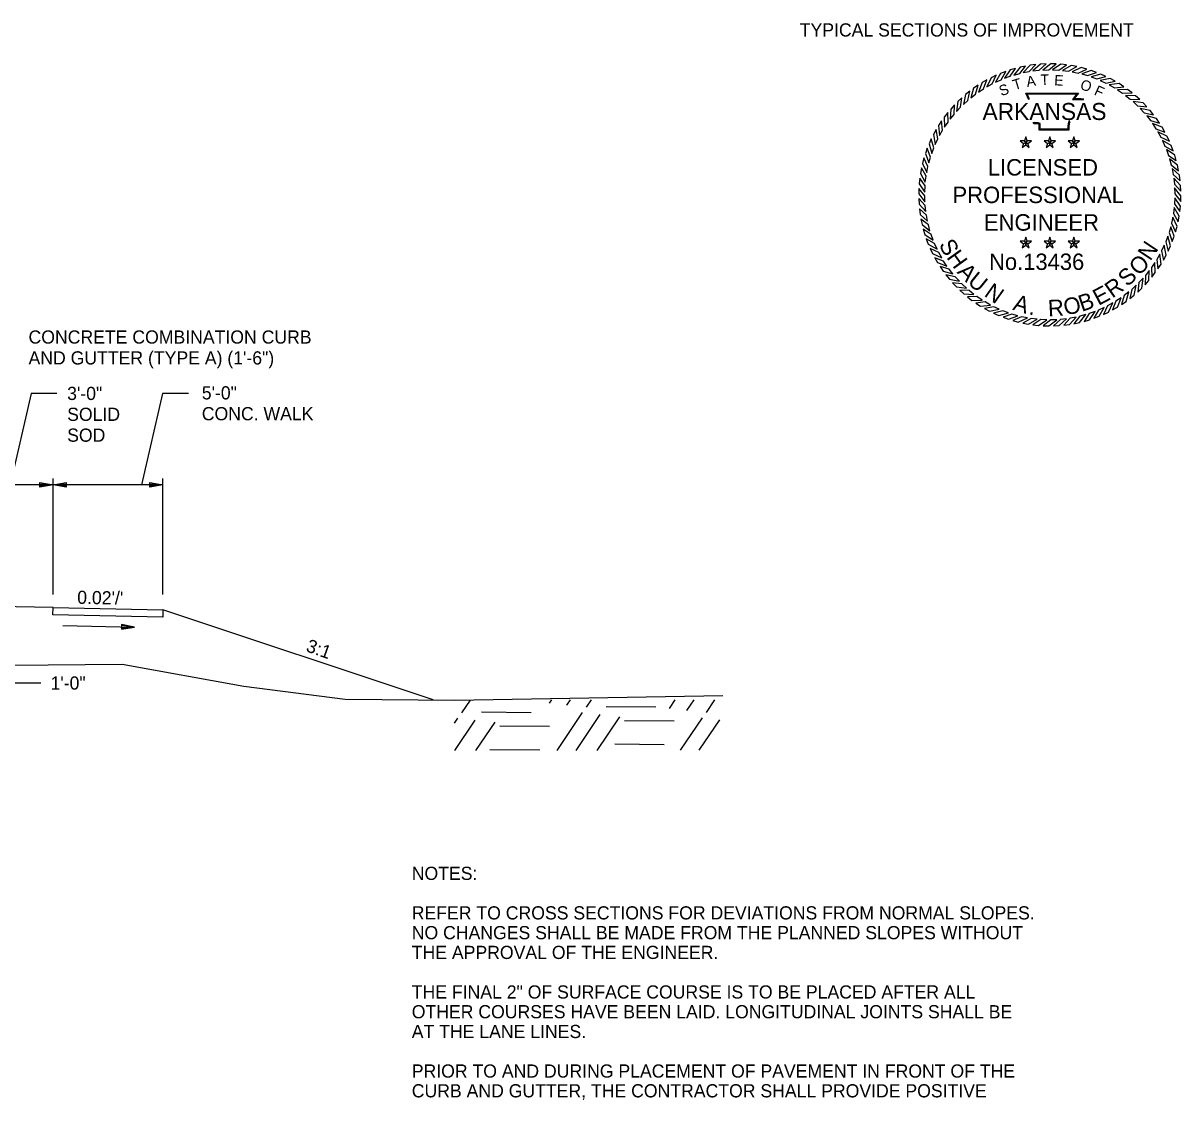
# Model space of a CAD drawing. Extents: x 1001270 to 1003428, y 1840152 to 1842912.
# Drawn here: x 1001375.8 to 1001428.5, y 1842848.3 to 1842897.3 of the extents above; entities that cross this region are included whole.
import ezdxf

# ---------------------------------------------------------------- set-up
doc = ezdxf.new("R2010")
doc.units = 0
for name, color, linetype in [('1', 7, 'Continuous'), ('19', 7, 'Continuous'), ('20', 7, 'Continuous'), ('8', 7, 'Continuous'), ('G-ANNO-SYMB', 7, 'Continuous')]:
    doc.layers.add(name, color=color, linetype=linetype)

# ---------------------------------------------------------------- blocks, each defined once
blk = doc.blocks.new('TM')
at = {"layer": '8'}
for p, q in [((-120.309, 21.181), (-119.787, -20.829)), ((0, 0), (-120.309, 21.181)), ((-31.382, 2.945), (-120.176, 10.512)), ((-119.787, -20.829), (0, 0)), ((-119.911, -10.826), (-31.307, -3.057))]:
    blk.add_line(p, q, dxfattribs=at)

msp = doc.modelspace()

# ---------------------------------------------------------------- linework, layer by layer
at = {"layer": '19'}
for p, q in [((1001376.15, 1842880.471), (1001375.194, 1842876.314)), ((1001377.329, 1842880.471), (1001376.15, 1842880.471)), ((1001382.133, 1842880.471), (1001381.176, 1842876.314)), ((1001383.312, 1842880.471), (1001382.133, 1842880.471)), ((1001382.155, 1842876.314), (1001372.655, 1842876.314)), ((1001376.555, 1842876.209), (1001376.555, 1842876.419)), ((1001376.555, 1842876.419), (1001377.155, 1842876.314)), ((1001376.555, 1842876.364), (1001376.995, 1842876.329)), ((1001377.155, 1842876.314), (1001376.555, 1842876.209)), ((1001376.995, 1842876.299), (1001376.555, 1842876.259)), ((1001377.155, 1842871.324), (1001377.155, 1842876.614)), ((1001377.155, 1842876.314), (1001377.755, 1842876.419)), ((1001377.755, 1842876.209), (1001377.155, 1842876.314)), ((1001377.315, 1842876.329), (1001377.755, 1842876.364)), ((1001377.755, 1842876.259), (1001377.315, 1842876.299)), ((1001377.755, 1842876.419), (1001377.755, 1842876.209)), ((1001381.555, 1842876.209), (1001381.555, 1842876.419)), ((1001381.555, 1842876.419), (1001382.155, 1842876.314)), ((1001381.555, 1842876.364), (1001381.995, 1842876.329)), ((1001382.155, 1842876.314), (1001381.555, 1842876.209)), ((1001381.995, 1842876.299), (1001381.555, 1842876.259)), ((1001382.155, 1842871.324), (1001382.155, 1842876.614)), ((1001377.156, 1842870.731), (1001374.155, 1842870.79)), ((1001377.143, 1842870.398), (1001377.156, 1842870.731)), ((1001377.156, 1842870.731), (1001382.155, 1842870.63)), ((1001377.156, 1842870.731), (1001377.156, 1842870.731)), ((1001382.155, 1842870.63), (1001382.142, 1842870.298)), ((1001394.456, 1842866.53), (1001382.155, 1842870.63)), ((1001382.142, 1842870.298), (1001377.143, 1842870.398)), ((1001375.155, 1842867.304), (1001376.604, 1842867.304)), ((1001375.155, 1842867.304), (1001376.604, 1842867.304)), ((1001395.763, 1842865.94), (1001396.155, 1842866.523)), ((1001399.749, 1842866.374), (1001399.855, 1842866.524)), ((1001400.544, 1842866.283), (1001400.709, 1842866.527)), ((1001401.439, 1842866.19), (1001401.665, 1842866.529)), ((1001405.203, 1842866.135), (1001405.465, 1842866.53)), ((1001405.998, 1842866.043), (1001406.329, 1842866.532)), ((1001406.893, 1842865.951), (1001407.274, 1842866.525)), ((1001396.652, 1842865.979), (1001398.912, 1842865.958)), ((1001400.101, 1842864.227), (1001401.253, 1842865.948)), ((1001400.956, 1842864.23), (1001402.048, 1842865.856)), ((1001401.911, 1842864.232), (1001402.943, 1842865.764)), ((1001402.326, 1842866.22), (1001404.587, 1842866.208)), ((1001395.424, 1842865.472), (1001395.578, 1842865.698)), ((1001395.446, 1842864.224), (1001396.372, 1842865.606)), ((1001396.401, 1842864.226), (1001397.268, 1842865.514)), ((1001397.492, 1842865.35), (1001399.752, 1842865.329)), ((1001403.157, 1842865.591), (1001405.427, 1842865.579)), ((1001405.711, 1842864.233), (1001406.707, 1842865.709)), ((1001406.566, 1842864.235), (1001407.502, 1842865.617)), ((1001397.039, 1842864.271), (1001399.31, 1842864.258)), ((1001402.715, 1842864.521), (1001404.974, 1842864.5))]:
    msp.add_line(p, q, dxfattribs=at)
for points in [[(1001312.476, 1842875.841), (1001316.166, 1842875.618), (1001320.348, 1842874.967), (1001324.071, 1842873.734), (1001333.313, 1842870.336), (1001335.792, 1842869.514), (1001340.406, 1842868.154), (1001345.958, 1842868.399), (1001354.686, 1842868.327), (1001358.509, 1842868.349), (1001367.384, 1842868.023), (1001373.548, 1842868.092), (1001380.3, 1842868.156), (1001385.837, 1842867.152), (1001390.452, 1842866.558), (1001395.437, 1842866.523)], [(1001395.437, 1842866.523), (1001407.642, 1842866.726)]]:
    msp.add_lwpolyline(points, dxfattribs=at)
at = {"layer": '20'}
msp.add_line((1001377.594, 1842869.911), (1001380.864, 1842869.846), dxfattribs=at)
at = {"layer": 'G-ANNO-SYMB'}
for points in [[(1001420.96, 1842895.277), (1001420.714, 1842895.205), (1001420.458, 1842894.826), (1001420.719, 1842894.92)], [(1001421.416, 1842895.382), (1001421.165, 1842895.329), (1001420.881, 1842894.971), (1001421.148, 1842895.045)], [(1001421.88, 1842895.45), (1001421.625, 1842895.417), (1001421.314, 1842895.083), (1001421.586, 1842895.135)], [(1001422.347, 1842895.482), (1001422.091, 1842895.469), (1001421.754, 1842895.16), (1001422.029, 1842895.191)], [(1001422.816, 1842895.477), (1001422.559, 1842895.484), (1001422.199, 1842895.203), (1001422.476, 1842895.212)], [(1001423.282, 1842895.435), (1001423.027, 1842895.463), (1001422.646, 1842895.21), (1001422.923, 1842895.197)], [(1001423.744, 1842895.357), (1001423.492, 1842895.404), (1001423.092, 1842895.183), (1001423.367, 1842895.148)], [(1001424.198, 1842895.243), (1001423.951, 1842895.31), (1001423.535, 1842895.12), (1001423.806, 1842895.064)], [(1001419.658, 1842894.755), (1001419.436, 1842894.627), (1001419.276, 1842894.199), (1001419.507, 1842894.351)], [(1001420.078, 1842894.963), (1001419.846, 1842894.853), (1001419.653, 1842894.438), (1001419.896, 1842894.572)], [(1001420.513, 1842895.137), (1001420.273, 1842895.046), (1001420.048, 1842894.648), (1001420.3, 1842894.762)], [(1001424.642, 1842895.093), (1001424.401, 1842895.18), (1001423.971, 1842895.023), (1001424.237, 1842894.946)], [(1001425.073, 1842894.909), (1001424.839, 1842895.014), (1001424.398, 1842894.892), (1001424.658, 1842894.794)], [(1001425.488, 1842894.692), (1001425.263, 1842894.815), (1001424.814, 1842894.728), (1001425.065, 1842894.61)], [(1001418.874, 1842894.243), (1001418.675, 1842894.082), (1001418.584, 1842893.634), (1001418.789, 1842893.82)], [(1001419.256, 1842894.514), (1001419.045, 1842894.369), (1001418.919, 1842893.93), (1001419.138, 1842894.1)], [(1001425.885, 1842894.443), (1001425.67, 1842894.584), (1001425.216, 1842894.532), (1001425.457, 1842894.395)], [(1001426.261, 1842894.164), (1001426.058, 1842894.321), (1001425.601, 1842894.305), (1001425.83, 1842894.149)], [(1001418.515, 1842893.942), (1001418.329, 1842893.766), (1001418.273, 1842893.312), (1001418.462, 1842893.515)], [(1001426.614, 1842893.856), (1001426.424, 1842894.028), (1001425.967, 1842894.048), (1001426.183, 1842893.875)], [(1001426.942, 1842893.521), (1001426.765, 1842893.708), (1001426.312, 1842893.763), (1001426.514, 1842893.574)], [(1001417.872, 1842893.262), (1001417.716, 1842893.059), (1001417.732, 1842892.602), (1001417.887, 1842892.831)], [(1001418.18, 1842893.615), (1001418.008, 1842893.425), (1001417.988, 1842892.968), (1001418.161, 1842893.184)], [(1001427.242, 1842893.162), (1001427.081, 1842893.361), (1001426.633, 1842893.453), (1001426.82, 1842893.248)], [(1001427.513, 1842892.78), (1001427.368, 1842892.992), (1001426.929, 1842893.118), (1001427.099, 1842892.899)], [(1001417.593, 1842892.886), (1001417.453, 1842892.671), (1001417.504, 1842892.217), (1001417.642, 1842892.457)], [(1001427.754, 1842892.378), (1001427.626, 1842892.6), (1001427.198, 1842892.76), (1001427.35, 1842892.529)], [(1001417.127, 1842892.074), (1001417.022, 1842891.84), (1001417.144, 1842891.399), (1001417.242, 1842891.659)], [(1001417.344, 1842892.489), (1001417.221, 1842892.264), (1001417.308, 1842891.815), (1001417.426, 1842892.066)], [(1001421.427, 1842891.894), (1001421.488, 1842891.978), (1001421.427, 1842892.167), (1001421.366, 1842891.978)], [(1001422.518, 1842891.894), (1001422.579, 1842891.978), (1001422.518, 1842892.167), (1001422.456, 1842891.978)], [(1001423.609, 1842891.894), (1001423.67, 1842891.978), (1001423.609, 1842892.167), (1001423.547, 1842891.978)], [(1001427.962, 1842891.958), (1001427.852, 1842892.19), (1001427.438, 1842892.383), (1001427.571, 1842892.14)], [(1001416.943, 1842891.643), (1001416.857, 1842891.401), (1001417.013, 1842890.972), (1001417.09, 1842891.238)], [(1001421.427, 1842891.894), (1001421.366, 1842891.978), (1001421.167, 1842891.978), (1001421.328, 1842891.862)], [(1001421.427, 1842891.894), (1001421.328, 1842891.862), (1001421.266, 1842891.674), (1001421.427, 1842891.79)], [(1001421.427, 1842891.894), (1001421.526, 1842891.862), (1001421.686, 1842891.978), (1001421.488, 1842891.978)], [(1001421.427, 1842891.894), (1001421.427, 1842891.79), (1001421.587, 1842891.674), (1001421.526, 1842891.862)], [(1001422.518, 1842891.894), (1001422.456, 1842891.978), (1001422.258, 1842891.978), (1001422.419, 1842891.862)], [(1001422.518, 1842891.894), (1001422.419, 1842891.862), (1001422.357, 1842891.674), (1001422.518, 1842891.79)], [(1001422.518, 1842891.894), (1001422.617, 1842891.862), (1001422.777, 1842891.978), (1001422.579, 1842891.978)], [(1001422.518, 1842891.894), (1001422.518, 1842891.79), (1001422.678, 1842891.674), (1001422.617, 1842891.862)], [(1001423.609, 1842891.894), (1001423.547, 1842891.978), (1001423.349, 1842891.978), (1001423.51, 1842891.862)], [(1001423.609, 1842891.894), (1001423.51, 1842891.862), (1001423.448, 1842891.674), (1001423.609, 1842891.79)], [(1001423.609, 1842891.894), (1001423.708, 1842891.862), (1001423.868, 1842891.978), (1001423.67, 1842891.978)], [(1001423.609, 1842891.894), (1001423.609, 1842891.79), (1001423.769, 1842891.674), (1001423.708, 1842891.862)], [(1001428.137, 1842891.524), (1001428.045, 1842891.763), (1001427.647, 1842891.988), (1001427.761, 1842891.736)], [(1001428.277, 1842891.076), (1001428.204, 1842891.323), (1001427.825, 1842891.578), (1001427.919, 1842891.318)], [(1001416.793, 1842891.199), (1001416.726, 1842890.952), (1001416.916, 1842890.535), (1001416.972, 1842890.807)], [(1001428.381, 1842890.62), (1001428.328, 1842890.871), (1001427.97, 1842891.156), (1001428.044, 1842890.888)], [(1001416.679, 1842890.745), (1001416.632, 1842890.493), (1001416.854, 1842890.093), (1001416.888, 1842890.368)], [(1001428.449, 1842890.156), (1001428.417, 1842890.411), (1001428.082, 1842890.723), (1001428.134, 1842890.45)], [(1001416.601, 1842890.283), (1001416.574, 1842890.028), (1001416.826, 1842889.647), (1001416.839, 1842889.923)], [(1001428.481, 1842889.689), (1001428.468, 1842889.945), (1001428.159, 1842890.282), (1001428.19, 1842890.007)], [(1001416.559, 1842889.816), (1001416.552, 1842889.56), (1001416.833, 1842889.2), (1001416.825, 1842889.477)], [(1001428.476, 1842889.221), (1001428.483, 1842889.477), (1001428.202, 1842889.837), (1001428.211, 1842889.56)], [(1001416.554, 1842889.348), (1001416.567, 1842889.092), (1001416.876, 1842888.755), (1001416.845, 1842889.03)], [(1001428.356, 1842888.292), (1001428.404, 1842888.544), (1001428.182, 1842888.944), (1001428.147, 1842888.669)], [(1001428.434, 1842888.754), (1001428.462, 1842889.009), (1001428.209, 1842889.39), (1001428.196, 1842889.114)], [(1001416.586, 1842888.881), (1001416.619, 1842888.626), (1001416.953, 1842888.314), (1001416.901, 1842888.587)], [(1001416.654, 1842888.417), (1001416.707, 1842888.166), (1001417.065, 1842887.881), (1001416.992, 1842888.149)], [(1001428.242, 1842887.838), (1001428.309, 1842888.086), (1001428.119, 1842888.502), (1001428.063, 1842888.23)], [(1001416.759, 1842887.961), (1001416.831, 1842887.714), (1001417.21, 1842887.459), (1001417.116, 1842887.719)], [(1001428.092, 1842887.394), (1001428.179, 1842887.636), (1001428.022, 1842888.065), (1001427.945, 1842887.799)], [(1001416.899, 1842887.514), (1001416.99, 1842887.274), (1001417.388, 1842887.049), (1001417.274, 1842887.301)], [(1001421.427, 1842887.326), (1001421.366, 1842887.41), (1001421.167, 1842887.41), (1001421.328, 1842887.294)], [(1001421.427, 1842887.326), (1001421.328, 1842887.294), (1001421.266, 1842887.105), (1001421.427, 1842887.222)], [(1001421.427, 1842887.326), (1001421.488, 1842887.41), (1001421.427, 1842887.599), (1001421.366, 1842887.41)], [(1001421.427, 1842887.326), (1001421.526, 1842887.294), (1001421.686, 1842887.41), (1001421.488, 1842887.41)], [(1001421.427, 1842887.326), (1001421.427, 1842887.222), (1001421.587, 1842887.105), (1001421.526, 1842887.294)], [(1001422.518, 1842887.326), (1001422.456, 1842887.41), (1001422.258, 1842887.41), (1001422.419, 1842887.294)], [(1001422.518, 1842887.326), (1001422.419, 1842887.294), (1001422.357, 1842887.105), (1001422.518, 1842887.222)], [(1001422.518, 1842887.326), (1001422.579, 1842887.41), (1001422.518, 1842887.599), (1001422.456, 1842887.41)], [(1001422.518, 1842887.326), (1001422.617, 1842887.294), (1001422.777, 1842887.41), (1001422.579, 1842887.41)], [(1001422.518, 1842887.326), (1001422.518, 1842887.222), (1001422.678, 1842887.105), (1001422.617, 1842887.294)], [(1001423.609, 1842887.326), (1001423.547, 1842887.41), (1001423.349, 1842887.41), (1001423.51, 1842887.294)], [(1001423.609, 1842887.326), (1001423.51, 1842887.294), (1001423.448, 1842887.105), (1001423.609, 1842887.222)], [(1001423.609, 1842887.326), (1001423.67, 1842887.41), (1001423.609, 1842887.599), (1001423.547, 1842887.41)], [(1001423.609, 1842887.326), (1001423.708, 1842887.294), (1001423.868, 1842887.41), (1001423.67, 1842887.41)], [(1001423.609, 1842887.326), (1001423.609, 1842887.222), (1001423.769, 1842887.105), (1001423.708, 1842887.294)], [(1001427.909, 1842886.963), (1001428.013, 1842887.197), (1001427.891, 1842887.638), (1001427.793, 1842887.379)], [(1001417.073, 1842887.079), (1001417.183, 1842886.847), (1001417.598, 1842886.654), (1001417.464, 1842886.897)], [(1001427.442, 1842886.151), (1001427.583, 1842886.366), (1001427.531, 1842886.82), (1001427.394, 1842886.58)], [(1001427.691, 1842886.548), (1001427.814, 1842886.773), (1001427.727, 1842887.222), (1001427.609, 1842886.971)], [(1001417.282, 1842886.659), (1001417.409, 1842886.437), (1001417.838, 1842886.277), (1001417.685, 1842886.508)], [(1001427.163, 1842885.775), (1001427.32, 1842885.978), (1001427.304, 1842886.435), (1001427.148, 1842886.206)], [(1001417.522, 1842886.257), (1001417.667, 1842886.045), (1001418.106, 1842885.919), (1001417.936, 1842886.138)], [(1001417.793, 1842885.875), (1001417.954, 1842885.676), (1001418.402, 1842885.584), (1001418.216, 1842885.789)], [(1001426.855, 1842885.422), (1001427.027, 1842885.613), (1001427.047, 1842886.069), (1001426.874, 1842885.853)], [(1001418.094, 1842885.516), (1001418.27, 1842885.329), (1001418.724, 1842885.274), (1001418.522, 1842885.463)], [(1001426.161, 1842884.794), (1001426.361, 1842884.955), (1001426.452, 1842885.403), (1001426.247, 1842885.217)], [(1001426.52, 1842885.095), (1001426.707, 1842885.271), (1001426.763, 1842885.725), (1001426.573, 1842885.523)], [(1001418.421, 1842885.181), (1001418.612, 1842885.009), (1001419.069, 1842884.989), (1001418.852, 1842885.162)], [(1001418.774, 1842884.873), (1001418.978, 1842884.716), (1001419.435, 1842884.732), (1001419.205, 1842884.888)], [(1001425.377, 1842884.282), (1001425.599, 1842884.41), (1001425.76, 1842884.838), (1001425.528, 1842884.686)], [(1001425.779, 1842884.523), (1001425.991, 1842884.668), (1001426.117, 1842885.107), (1001425.898, 1842884.937)], [(1001419.15, 1842884.594), (1001419.365, 1842884.454), (1001419.82, 1842884.505), (1001419.579, 1842884.643)], [(1001419.547, 1842884.345), (1001419.772, 1842884.222), (1001420.221, 1842884.309), (1001419.97, 1842884.427)], [(1001419.962, 1842884.128), (1001420.196, 1842884.023), (1001420.637, 1842884.145), (1001420.378, 1842884.243)], [(1001424.076, 1842883.76), (1001424.322, 1842883.832), (1001424.577, 1842884.211), (1001424.317, 1842884.117)], [(1001424.523, 1842883.9), (1001424.762, 1842883.991), (1001424.988, 1842884.389), (1001424.735, 1842884.275)], [(1001424.957, 1842884.074), (1001425.189, 1842884.184), (1001425.382, 1842884.599), (1001425.14, 1842884.465)], [(1001420.393, 1842883.944), (1001420.635, 1842883.858), (1001421.064, 1842884.014), (1001420.798, 1842884.091)], [(1001420.837, 1842883.794), (1001421.085, 1842883.727), (1001421.501, 1842883.917), (1001421.229, 1842883.973)], [(1001421.291, 1842883.68), (1001421.543, 1842883.633), (1001421.943, 1842883.854), (1001421.668, 1842883.889)], [(1001421.753, 1842883.602), (1001422.008, 1842883.574), (1001422.39, 1842883.827), (1001422.113, 1842883.84)], [(1001422.22, 1842883.56), (1001422.476, 1842883.553), (1001422.837, 1842883.834), (1001422.56, 1842883.825)], [(1001422.688, 1842883.555), (1001422.944, 1842883.568), (1001423.282, 1842883.877), (1001423.006, 1842883.846)], [(1001423.156, 1842883.587), (1001423.41, 1842883.62), (1001423.722, 1842883.954), (1001423.45, 1842883.902)], [(1001423.619, 1842883.655), (1001423.87, 1842883.708), (1001424.155, 1842884.066), (1001423.887, 1842883.993)]]:
    msp.add_lwpolyline(points, close=True, dxfattribs=at)
for points in [[(1001421.562, 1842893.849), (1001421.423, 1842894.15), (1001423.829, 1842894.151), (1001423.628, 1842893.899), (1001423.792, 1842893.901), (1001423.928, 1842893.902), (1001424.065, 1842893.888)], [(1001421.596, 1842893.864), (1001421.482, 1842894.112), (1001423.75, 1842894.113), (1001423.548, 1842893.859), (1001423.792, 1842893.863), (1001423.926, 1842893.864), (1001424.06, 1842893.85)], [(1001423.45, 1842892.84), (1001423.409, 1842892.807), (1001423.395, 1842892.757), (1001423.382, 1842892.632), (1001423.382, 1842892.466), (1001422.038, 1842892.466), (1001422.038, 1842892.69), (1001422.038, 1842892.74), (1001421.984, 1842892.757), (1001421.793, 1842892.757), (1001421.759, 1842892.809)], [(1001423.426, 1842892.87), (1001423.375, 1842892.829), (1001423.358, 1842892.764), (1001423.344, 1842892.634), (1001423.344, 1842892.504), (1001422.077, 1842892.504), (1001422.077, 1842892.69), (1001422.077, 1842892.768), (1001421.99, 1842892.795), (1001421.813, 1842892.795), (1001421.791, 1842892.829)]]:
    msp.add_lwpolyline(points, dxfattribs=at)

# ---------------------------------------------------------------- block references
at = {"layer": '19', "xscale": 0.0050063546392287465, "yscale": 0.005006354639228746, "rotation": -1.1310771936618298}
msp.add_blockref('TM', (1001380.864, 1842869.843), dxfattribs=at)

# ---------------------------------------------------------------- texts
at = {"layer": '1'}
msp.add_text('TYPICAL SECTIONS OF IMPROVEMENT', height=0.6, dxfattribs=at).set_placement((1001411.138, 1842896.727))
at = {"layer": '19'}
for s, p in [('CONCRETE COMBINATION CURB', (1001376.037, 1842882.747)), ('AND GUTTER (TYPE A) (1\'-6")', (1001376.037, 1842881.797)), ('3\'-0"', (1001377.795, 1842880.18)), ('5\'-0"', (1001383.923, 1842880.207)), ('SOLID ', (1001377.795, 1842879.23)), ('CONC. WALK', (1001383.923, 1842879.257)), ('SOD', (1001377.795, 1842878.28)), ('NOTES:', (1001393.479, 1842858.333)), ('REFER TO CROSS SECTIONS FOR DEVIATIONS FROM NORMAL SLOPES.', (1001393.479, 1842856.533)), ('NO CHANGES SHALL BE MADE FROM THE PLANNED SLOPES WITHOUT', (1001393.479, 1842855.633)), ('THE APPROVAL OF THE ENGINEER.', (1001393.479, 1842854.733)), ('THE FINAL 2" OF SURFACE COURSE IS TO BE PLACED AFTER ALL', (1001393.479, 1842852.933)), ('OTHER COURSES HAVE BEEN LAID. LONGITUDINAL JOINTS SHALL BE', (1001393.479, 1842852.033)), ('AT THE LANE LINES.', (1001393.479, 1842851.133)), ('PRIOR TO AND DURING PLACEMENT OF PAVEMENT IN FRONT OF THE', (1001393.479, 1842849.333)), ('CURB AND GUTTER, THE CONTRACTOR SHALL PROVIDE POSITIVE', (1001393.479, 1842848.433))]:
    msp.add_text(s, height=0.6, dxfattribs=at).set_placement(p)
for s, rotation, p in [("0.02'/'", 358.8515, (1001378.248, 1842870.903)), ('3:1', 340.4943, (1001388.628, 1842868.75)), ('1\'-0"', 360, (1001377.039, 1842866.996))]:
    msp.add_text(s, height=0.6, rotation=rotation, dxfattribs=at).set_placement(p)
at = {"layer": 'G-ANNO-SYMB'}
for s, height, rotation, p in [('T', 0.475, 16.9015, (1001420.912, 1842894.277)), ('A', 0.475, 8.6788, (1001421.489, 1842894.428)), ('T', 0.475, 1.4789, (1001422.102, 1842894.522)), ('E', 0.475, 356.672, (1001422.709, 1842894.508)), ('O', 0.475, 341.2218, (1001423.862, 1842894.345)), ('S', 0.475, 19.7726, (1001420.309, 1842894.006)), ('F', 0.475, 335.3628, (1001424.501, 1842894.095)), ('ARKANSAS', 0.7747, 360, (1001419.456, 1842892.927)), ('LICENSED', 0.75, 360, (1001419.696, 1842890.398)), ('PROFESSIONAL', 0.75, 360, (1001418.089, 1842889.144)), ('ENGINEER', 0.75, 360, (1001419.518, 1842887.889)), ('S', 0.75, 298.1636, (1001417.45, 1842887.259)), ('N', 0.75, 56.1007, (1001427.092, 1842886.475)), ('H', 0.75, 305.619, (1001417.792, 1842886.671)), ('No.13436', 0.747, 360, (1001419.754, 1842886.101)), ('A', 0.75, 313.4472, (1001418.268, 1842885.986)), ('O', 0.75, 44.7757, (1001426.571, 1842885.8)), ('U', 0.75, 320.9026, (1001418.735, 1842885.497)), ('S', 0.75, 43.4878, (1001426.055, 1842885.302)), ('N', 0.75, 324.9326, (1001419.491, 1842884.939)), ('E', 0.75, 27.8315, (1001424.732, 1842884.46)), ('R', 0.75, 35.6597, (1001425.366, 1842884.793)), ('A', 0.75, 343.0991, (1001420.799, 1842884.295)), ('R', 0.75, 3.2287, (1001422.455, 1842883.982)), ('O', 0.75, 11.4296, (1001423.223, 1842884.03)), ('B', 0.75, 18.885, (1001423.974, 1842884.189)), ('.', 0.75, 351.3, (1001421.536, 1842884.077))]:
    msp.add_text(s, height=height, rotation=rotation, dxfattribs=at).set_placement(p)

doc.saveas('drawing.dxf')
